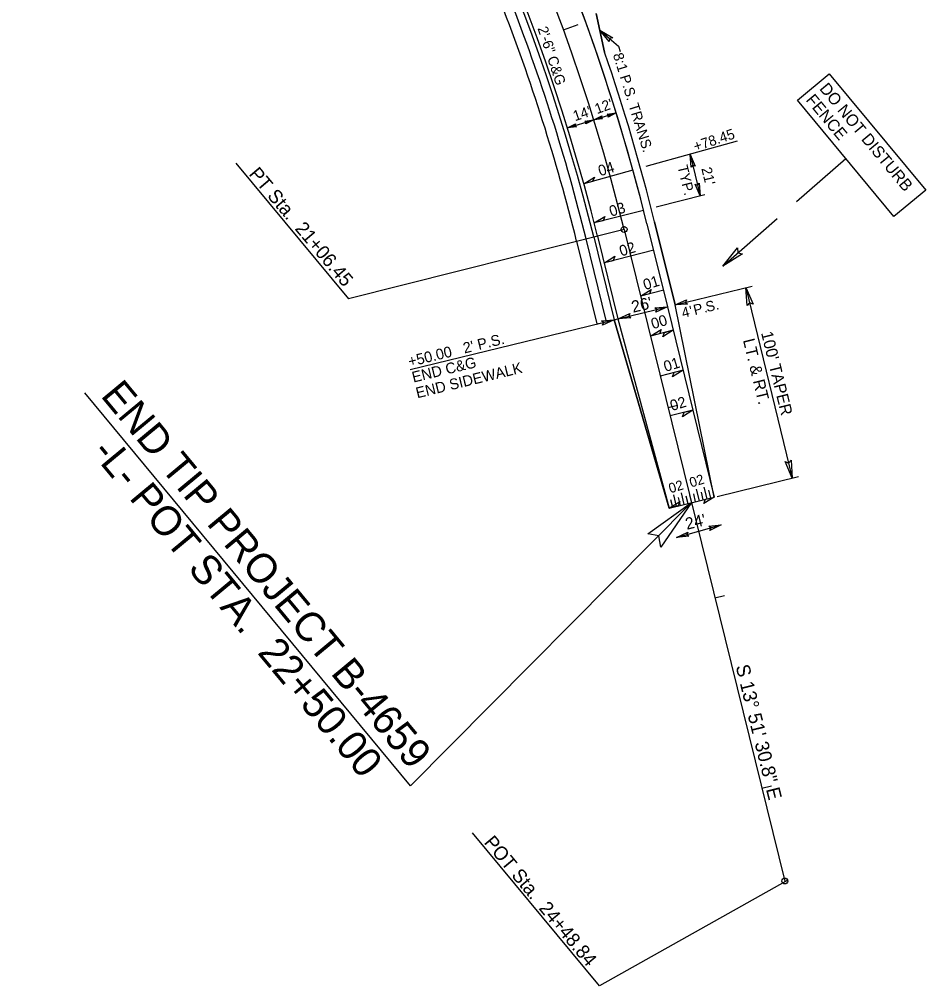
# Model space of a CAD drawing. Extents: x 2057680 to 2059216, y 687940 to 689338.
# Drawn here: x 2058753.8 to 2059216.3, y 687940.4 to 688433.4 of the extents above; entities that cross this region are included whole.
import ezdxf

# ---------------------------------------------------------------- set-up
doc = ezdxf.new("R2010")
doc.units = 0
for name, color, linetype in [('Cogo Default Point CELL', 7, 'Continuous'), ('COGO Default Point Elevation', 7, 'Continuous'), ('COGO Default Point Number', 7, 'Continuous'), ('Exist DTM Breakline Cogo Elevation', 7, 'Continuous'), ('Exist DTM Regular Point Cogo Number', 7, 'Continuous'), ('Exist DTM Ridgeline Cogo Number', 7, 'Continuous'), ('Exist Other Culture Located Object CELL', 7, 'Continuous'), ('Exist Other Culture Located Object Leader', 7, 'Continuous'), ('Exist Roads EOP Cogo Elevation', 7, 'Continuous'), ('Exist Roads EOP Cogo Number', 7, 'Continuous'), ('Exist Roads EOP Cogo Point CELL', 7, 'Continuous'), ('Exist Structure Major Bridge WW Cogo Point CELL', 7, 'Continuous'), ('Exist Structure Major Deck Tunnel Box Culvert Cogo Elevation', 7, 'Continuous'), ('Exist Structure Major Deck Tunnel Box Culvert Cogo Number', 7, 'Continuous'), ('Exist Structure Major Deck Tunnel Box Culvert Cogo Point CELL', 7, 'Continuous'), ('Exist Structure Minor Pipes HDPE 36 Inch', 7, 'Continuous'), ('Prop Conc 2ft 6in Curb and Gutter', 7, 'Continuous')]:
    doc.layers.add(name, color=color, linetype=linetype)

msp = doc.modelspace()

# ---------------------------------------------------------------- linework, layer by layer
at = {"layer": 'Cogo Default Point CELL'}
msp.add_line((2059062.46, 688326.22), (2059144.47, 687993.8), dxfattribs=at)
msp.add_arc((2058091.57, 688086.7), 1000, 13.85856, 62.50587, dxfattribs=at)
at = {"layer": 'COGO Default Point Elevation'}
msp.add_line((2058864.32, 688360.06), (2058921.74, 688290.82), dxfattribs=at)
at = {"layer": 'Exist DTM Breakline Cogo Elevation'}
for p, q in [((2059096.15, 688364.46), (2059101.27, 688343.46)), ((2059124.6, 688296.55), (2059148.28, 688199.39)), ((2058953.37, 688042.39), (2058787.18, 688242.8)), ((2059099.28, 688193.72), (2059100.73, 688187.8)), ((2059103.17, 688194.67), (2059104.61, 688188.75)), ((2059105.59, 688193.2), (2059106.56, 688189.22)), ((2059086.15, 688188.47), (2059087.13, 688184.48)), ((2059087.62, 688190.88), (2059089.07, 688184.96)), ((2059090.04, 688189.41), (2059091.01, 688185.43)), ((2059091.51, 688191.83), (2059092.95, 688185.91)), ((2059093.93, 688190.36), (2059094.9, 688186.38)), ((2059095.87, 688190.83), (2059096.84, 688186.85)), ((2059097.81, 688191.31), (2059098.78, 688187.33)), ((2059101.7, 688192.26), (2059102.67, 688188.27)), ((2058953.37, 688042.39), (2059096.84, 688186.85))]:
    msp.add_line(p, q, dxfattribs=at)
at = {"layer": 'Exist DTM Regular Point Cogo Number'}
msp.add_lwpolyline([(2059054.9, 688422.04), (2059050.02, 688427.88), (2059056.63, 688424.01), (2059055.03, 688423.61)], close=True, dxfattribs=at)
at = {"layer": 'Exist DTM Ridgeline Cogo Number'}
for p, q in [((2059066.94, 688356.51), (2059041.88, 688349.58)), ((2059072.39, 688335.97), (2059047.19, 688329.57)), ((2059077.56, 688315.62), (2059052.36, 688309.21)), ((2059082.73, 688295.26), (2059070.84, 688292.24)), ((2059070.84, 688292.24), (2059070.84, 688292.24)), ((2059070.84, 688292.24), (2059070.84, 688292.24)), ((2059087.49, 688274.81), (2059075.87, 688271.85)), ((2059092.51, 688254.41), (2059080.9, 688251.46)), ((2059097.53, 688234.02), (2059085.93, 688231.07))]:
    msp.add_line(p, q, dxfattribs=at)
for points in [[(2059041.88, 688349.58), (2059047.26, 688352.91), (2059046.38, 688350.64)], [(2059047.19, 688329.57), (2059052.57, 688332.89), (2059051.69, 688330.63)], [(2059052.36, 688309.21), (2059057.74, 688312.54), (2059056.86, 688310.28)], [(2059070.84, 688292.24), (2059076.22, 688295.57), (2059075.34, 688293.31)], [(2059076.01, 688271.89), (2059081.39, 688275.22), (2059080.51, 688272.95)], [(2059087.49, 688274.81), (2059082.12, 688271.47), (2059083, 688273.73)], [(2059092.51, 688254.41), (2059087.14, 688251.08), (2059088.01, 688253.34)], [(2059097.53, 688234.02), (2059092.16, 688230.69), (2059093.03, 688232.95)], [(2059108.44, 688189.68), (2059103.07, 688186.34), (2059103.95, 688188.61)], [(2059085.47, 688184.08), (2059090.85, 688187.41), (2059089.97, 688185.15)]]:
    msp.add_lwpolyline(points, close=True, dxfattribs=at)
at = {"layer": 'Exist Other Culture Located Object CELL'}
for p, q in [((2059050.02, 688427.88), (2059059.53, 688419.79)), ((2059059.53, 688419.79), (2059060.37, 688417.02)), ((2059046.92, 688382.15), (2059058.39, 688385.7)), ((2059033.55, 688378.02), (2059046.92, 688382.15)), ((2059120.13, 688371.23), (2059073.59, 688358.35)), ((2059150.42, 688340.48), (2059175.53, 688362.47)), ((2059103.64, 688343.91), (2059078.86, 688337.62)), ((2059112.8, 688307.55), (2059140.54, 688331.83)), ((2059088.43, 688287.73), (2059127.78, 688297.32)), ((2059059.44, 688280.66), (2059084.55, 688286.78)), ((2058953.29, 688254.79), (2059057.34, 688280.15)), ((2059109.87, 688190.03), (2059151.46, 688200.17)), ((2059089.19, 688169.03), (2059112.03, 688175.53))]:
    msp.add_line(p, q, dxfattribs=at)
msp.add_lwpolyline([(2059167.13, 688405.58), (2059216.34, 688346.24), (2059200.14, 688332.8), (2059150.93, 688392.15)], close=True, dxfattribs=at)
at = {"layer": 'Exist Roads EOP Cogo Elevation'}
for p, q in [((2059053.31, 688279.8), (2059043.04, 688321.43)), ((2059038.18, 688320.24), (2059048.6, 688278.02)), ((2059048.6, 688278.02), (2059051.9, 688278.83))]:
    msp.add_line(p, q, dxfattribs=at)
msp.add_lwpolyline([(2059051.9, 688278.83), (2059050.97, 688279.6), (2059053.31, 688279.8)], dxfattribs=at)
for radius in [975, 980]:
    msp.add_arc((2058091.57, 688086.7), radius, 13.85856, 21.36309, dxfattribs=at)
at = {"layer": 'Exist Roads EOP Cogo Number'}
for p, q in [((2059084.86, 688235.4), (2059089.72, 688236.59)), ((2059108.82, 688138.31), (2059113.67, 688139.51)), ((2059132.77, 688041.22), (2059137.62, 688042.42))]:
    msp.add_line(p, q, dxfattribs=at)
at = {"layer": 'Exist Roads EOP Cogo Point CELL'}
for p, q in [((2059062.46, 688326.22), (2058921.74, 688290.82)), ((2059049.82, 687940.41), (2058985.13, 688018.42)), ((2059145.92, 687994.16), (2059049.82, 687940.41))]:
    msp.add_line(p, q, dxfattribs=at)
for centre in [(2059062.46, 688326.22), (2059144.47, 687993.8)]:
    msp.add_circle(centre, 1.5, dxfattribs=at)
at = {"layer": 'Exist Structure Major Bridge WW Cogo Point CELL'}
for p, q in [((2059048.14, 688436.43), (2059052.51, 688416.6)), ((2059077.99, 688330.06), (2059088.43, 688287.74)), ((2059108.44, 688189.68), (2059088.43, 688287.74)), ((2059057.34, 688280.15), (2059085.47, 688184.08))]:
    msp.add_line(p, q, dxfattribs=at)
msp.add_arc((2058091.57, 688086.7), 1016, 13.85856, 18.94802, dxfattribs=at)
at = {"layer": 'Exist Structure Major Deck Tunnel Box Culvert Cogo Elevation'}
for p, q in [((2059052.51, 688416.6), (2059048.14, 688436.43)), ((2059074.11, 688329.1), (2059084.55, 688286.78)), ((2059088.43, 688287.74), (2059077.99, 688330.06)), ((2059084.55, 688286.78), (2059108.44, 688189.68)), ((2059108.44, 688189.68), (2059088.43, 688287.74)), ((2059057.34, 688280.15), (2059059.29, 688280.63)), ((2059085.47, 688184.08), (2059057.34, 688280.15)), ((2059059.29, 688280.63), (2059085.47, 688184.08))]:
    msp.add_line(p, q, dxfattribs=at)
for radius, end in [(1012, 37.17732), (1016, 18.94802)]:
    msp.add_arc((2058091.57, 688086.7), radius, 13.85856, end, dxfattribs=at)
at = {"layer": 'Exist Structure Major Deck Tunnel Box Culvert Cogo Number'}
for p, q in [((2059074.11, 688329.1), (2059084.55, 688286.78)), ((2059048.86, 688322.87), (2059059.29, 688280.63)), ((2059084.55, 688286.78), (2059108.44, 688189.68)), ((2059059.29, 688280.63), (2059085.47, 688184.08)), ((2059085.47, 688184.08), (2059108.44, 688189.68))]:
    msp.add_line(p, q, dxfattribs=at)
for radius in [1012, 986]:
    msp.add_arc((2058091.57, 688086.7), radius, 13.85856, 62.50587, dxfattribs=at)
at = {"layer": 'Exist Structure Major Deck Tunnel Box Culvert Cogo Point CELL'}
msp.add_line((2059031.51, 688428.02), (2059039.03, 688430.75), dxfattribs=at)
at = {"layer": 'Exist Structure Minor Pipes HDPE 36 Inch'}
for points in [[(2059053.86, 688385.11), (2059058.39, 688385.7), (2059054.3, 688383.6), (2059054.61, 688384.53)], [(2059038.08, 688378.6), (2059033.55, 688378.02), (2059037.64, 688380.12), (2059037.32, 688379.18)], [(2059042.4, 688381.56), (2059046.92, 688382.15), (2059042.84, 688380.05), (2059043.15, 688380.99)], [(2059051.45, 688382.74), (2059046.92, 688382.15), (2059051.01, 688384.25), (2059050.7, 688383.32)], [(2059096.6, 688358.09), (2059096.15, 688364.46), (2059098.75, 688358.58), (2059097.47, 688359.09)], [(2059100.81, 688349.84), (2059101.27, 688343.46), (2059098.66, 688349.35), (2059099.94, 688348.83)], [(2059122.93, 688313.74), (2059112.8, 688307.55), (2059120.28, 688316.86), (2059120.53, 688314.31)], [(2059125.22, 688287.44), (2059124.6, 688296.55), (2059128.3, 688288.13), (2059126.47, 688288.87)], [(2059078.18, 688286.23), (2059084.55, 688286.78), (2059078.71, 688284.09), (2059079.2, 688285.37)], [(2059094.81, 688288.17), (2059088.43, 688287.73), (2059094.32, 688290.32), (2059093.81, 688289.04)], [(2059065.81, 688281.22), (2059059.44, 688280.66), (2059065.28, 688283.36), (2059064.79, 688282.07)], [(2059050.97, 688279.6), (2059057.34, 688280.15), (2059051.5, 688277.45), (2059052, 688278.74)], [(2059147.66, 688208.5), (2059148.28, 688199.39), (2059144.58, 688207.81), (2059146.41, 688207.07)], [(2059074.57, 688170.9), (2059096.84, 688186.85), (2059081.19, 688164.16), (2059080.19, 688169.98)], [(2059105.67, 688174.83), (2059112.03, 688175.53), (2059106.25, 688172.7), (2059106.71, 688174)], [(2059095.55, 688169.73), (2059089.19, 688169.03), (2059094.97, 688171.86), (2059094.51, 688170.56)]]:
    msp.add_lwpolyline(points, close=True, dxfattribs=at)
at = {"layer": 'Prop Conc 2ft 6in Curb and Gutter'}
for p, q in [((2059046.92, 688322.39), (2059057.34, 688280.15)), ((2059057.34, 688280.15), (2059059.29, 688280.63))]:
    msp.add_line(p, q, dxfattribs=at)
msp.add_arc((2058091.57, 688086.7), 984, 13.85856, 33.91785, dxfattribs=at)

# ---------------------------------------------------------------- texts
at = {"layer": 'COGO Default Point Number'}
msp.add_text('S 13%%d 51\' 30.8" E', height=7, rotation=283.8586, dxfattribs=at).set_placement((2059119.34, 688103.36))
at = {"layer": 'Exist DTM Breakline Cogo Elevation'}
for s, height, rotation, p in [('2\'-6" C&G', 5.25, 288.0526, (2059018.21, 688428.87)), ('8:1 P.S. TRANS.', 5.25, 287.2474, (2059056.67, 688415.41)), ('DO NOT DISTURB', 6, 309.6672, (2059161.82, 688397.92)), ('FENCE', 6, 309.6672, (2059154.9, 688392.18)), ("12'", 5.25, 20.1819, (2059048.61, 688385.02)), ("14'", 5.25, 18.6535, (2059037.39, 688381.42)), ('+78.45', 5.25, 18.5918, (2059098.88, 688365.91)), ('TYP.', 5.25, 283.7003, (2059089.64, 688358.35)), ("21'", 5.25, 283.7003, (2059101.82, 688357.33)), ("26'", 6, 13.7003, (2059066.99, 688283.69)), ('4', 5.25, 13.7003, (2059092.48, 688281.02)), ("'", 5.25, 13.7003, (2059096.58, 688282.02)), ('P', 5.25, 13.7003, (2059098.51, 688282.49)), ('S', 5.25, 13.7003, (2059104.77, 688284.02)), ('.', 5.25, 13.7003, (2059109.43, 688285.15)), ('.', 5.25, 13.7003, (2059103.41, 688283.69)), ("+50.00   2' P.S.", 5.5, 13.7003, (2058952.98, 688256.09)), ("100' TAPER", 6, 283.7003, (2059132.29, 688273.46)), ('LT. & RT.', 6, 283.7003, (2059123.04, 688269.79)), ('END C&G', 5.5, 13.7003, (2058954.93, 688248.07)), ('END SIDEWALK', 5.5, 13.7003, (2058956.89, 688240.06)), ('END TIP PROJECT B-4659 ', 15, 309.6672, (2058794.92, 688241.28)), ('-L- POT STA.  22+50.00  ', 15, 309.6672, (2058790.28, 688212.28)), ("24'", 6, 13.7003, (2059094.48, 688172.97))]:
    msp.add_text(s, height=height, rotation=rotation, dxfattribs=at).set_placement(p)
at = {"layer": 'Exist Other Culture Located Object Leader'}
for s, height, p in [('04', 5.5, (2059050.19, 688353.33)), ('03', 5.5, (2059055.82, 688332.67)), ('02', 5.5, (2059060.99, 688312.42)), ('01', 5.5, (2059073.14, 688295.23)), ('00', 5.5, (2059077.17, 688275.28)), ('01', 5.5, (2059083.59, 688253.51)), ('02', 5.5, (2059086.88, 688233.54)), ('02', 5, (2059086.08, 688191.58)), ('02', 5, (2059096.67, 688194.52))]:
    msp.add_text(s, height=height, rotation=17.1762, dxfattribs=at).set_placement(p)
at = {"layer": 'Exist Roads EOP Cogo Point CELL'}
for s, rotation, p in [('PT Sta.  21+06.45', 310.1685, (2058870.6, 688354.31)), ('POT Sta.  24+48.84', 309.822, (2058990.6, 688013.34))]:
    msp.add_text(s, height=7, rotation=rotation, dxfattribs=at).set_placement(p)

doc.saveas('drawing.dxf')
